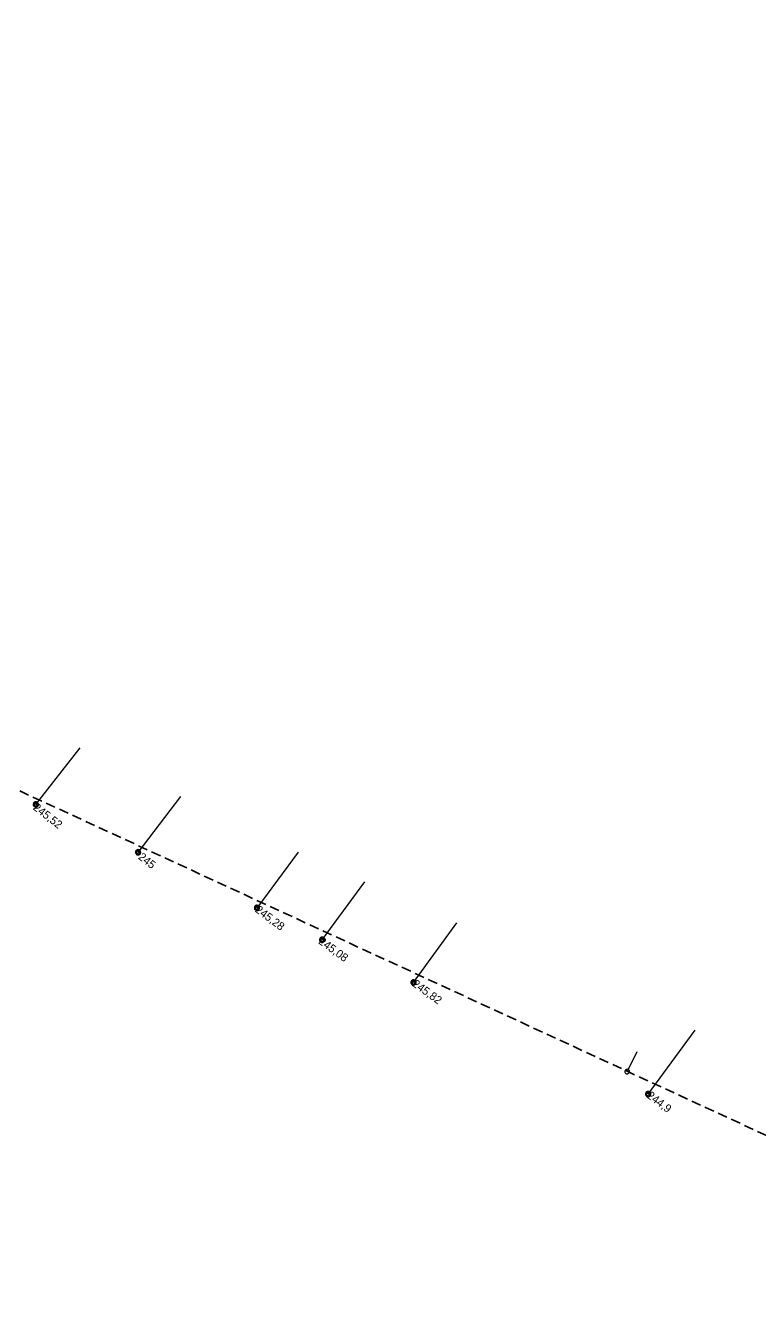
# Model space of a CAD drawing. Extents: x -735085 to -733500, y -1044153 to -1043402.
# Drawn here: x -734516.4 to -734443.8, y -1043690.4 to -1043562.9 of the extents above; entities that cross this region are included whole.
import ezdxf

# ---------------------------------------------------------------- set-up
doc = ezdxf.new("R2010")
doc.units = 0
doc.header["$LTSCALE"] = 0.32
doc.linetypes.add('MEDIUM_DASHED', pattern=[4.5, 3, -1.5])
doc.layers.add('16', color=7, linetype='Continuous')
for name, color, linetype, lineweight in [('18', 7, 'Continuous', 13), ('49', 7, 'Continuous', 13), ('63', 7, 'MEDIUM_DASHED', 25), ('8', 7, 'Continuous', 13)]:
    doc.layers.add(name, color=color, linetype=linetype, lineweight=lineweight)

msp = doc.modelspace()

# ---------------------------------------------------------------- linework, layer by layer
at = {"layer": '18'}
for points in [[(-734515.115, -1043640.239), (-734515.12, -1043640.183), (-734515.137, -1043640.13), (-734515.166, -1043640.081), (-734515.205, -1043640.04), (-734515.25, -1043640.008), (-734515.303, -1043639.986), (-734515.358, -1043639.975), (-734515.414, -1043639.977), (-734515.468, -1043639.99), (-734515.519, -1043640.015), (-734515.564, -1043640.05), (-734515.6, -1043640.093), (-734515.625, -1043640.143), (-734515.64, -1043640.198), (-734515.642, -1043640.254), (-734515.634, -1043640.309), (-734515.613, -1043640.362), (-734515.581, -1043640.408), (-734515.541, -1043640.447), (-734515.494, -1043640.477), (-734515.441, -1043640.496), (-734515.385, -1043640.503), (-734515.328, -1043640.499), (-734515.274, -1043640.482), (-734515.225, -1043640.455), (-734515.184, -1043640.417), (-734515.151, -1043640.372), (-734515.127, -1043640.321), (-734515.115, -1043640.266)], [(-734515.174, -1043640.242), (-734515.179, -1043640.193), (-734515.198, -1043640.147), (-734515.225, -1043640.106), (-734515.262, -1043640.073), (-734515.306, -1043640.051), (-734515.355, -1043640.039), (-734515.404, -1043640.039), (-734515.451, -1043640.051), (-734515.495, -1043640.074), (-734515.532, -1043640.107), (-734515.561, -1043640.148), (-734515.578, -1043640.195), (-734515.583, -1043640.244), (-734515.576, -1043640.293), (-734515.559, -1043640.339), (-734515.531, -1043640.379), (-734515.494, -1043640.412), (-734515.45, -1043640.434), (-734515.401, -1043640.446), (-734515.352, -1043640.445), (-734515.304, -1043640.433), (-734515.261, -1043640.409), (-734515.223, -1043640.376), (-734515.196, -1043640.335), (-734515.179, -1043640.288)], [(-734515.233, -1043640.246), (-734515.239, -1043640.204), (-734515.255, -1043640.166), (-734515.284, -1043640.135), (-734515.318, -1043640.112), (-734515.358, -1043640.101), (-734515.401, -1043640.101), (-734515.441, -1043640.113), (-734515.475, -1043640.136), (-734515.502, -1043640.168), (-734515.519, -1043640.206), (-734515.524, -1043640.247), (-734515.519, -1043640.289), (-734515.5, -1043640.326), (-734515.473, -1043640.358), (-734515.436, -1043640.38), (-734515.397, -1043640.391), (-734515.355, -1043640.39), (-734515.315, -1043640.377), (-734515.281, -1043640.354), (-734515.254, -1043640.321), (-734515.238, -1043640.283)], [(-734504.972, -1043644.989), (-734504.978, -1043644.933), (-734504.995, -1043644.88), (-734505.024, -1043644.831), (-734505.062, -1043644.79), (-734505.108, -1043644.758), (-734505.16, -1043644.736), (-734505.215, -1043644.725), (-734505.271, -1043644.727), (-734505.326, -1043644.74), (-734505.377, -1043644.765), (-734505.421, -1043644.8), (-734505.457, -1043644.843), (-734505.482, -1043644.893), (-734505.497, -1043644.948), (-734505.5, -1043645.004), (-734505.491, -1043645.059), (-734505.47, -1043645.112), (-734505.439, -1043645.158), (-734505.399, -1043645.197), (-734505.351, -1043645.227), (-734505.298, -1043645.246), (-734505.242, -1043645.253), (-734505.186, -1043645.249), (-734505.132, -1043645.232), (-734505.083, -1043645.205), (-734505.041, -1043645.167), (-734505.008, -1043645.122), (-734504.985, -1043645.071), (-734504.973, -1043645.016)], [(-734505.031, -1043644.992), (-734505.037, -1043644.943), (-734505.055, -1043644.897), (-734505.083, -1043644.856), (-734505.12, -1043644.823), (-734505.164, -1043644.801), (-734505.212, -1043644.789), (-734505.261, -1043644.789), (-734505.309, -1043644.801), (-734505.353, -1043644.824), (-734505.39, -1043644.857), (-734505.418, -1043644.898), (-734505.435, -1043644.945), (-734505.441, -1043644.994), (-734505.434, -1043645.043), (-734505.416, -1043645.089), (-734505.388, -1043645.129), (-734505.351, -1043645.162), (-734505.307, -1043645.184), (-734505.258, -1043645.196), (-734505.209, -1043645.195), (-734505.161, -1043645.183), (-734505.118, -1043645.159), (-734505.081, -1043645.126), (-734505.053, -1043645.085), (-734505.037, -1043645.038)], [(-734505.09, -1043644.996), (-734505.096, -1043644.954), (-734505.113, -1043644.916), (-734505.141, -1043644.885), (-734505.176, -1043644.862), (-734505.216, -1043644.851), (-734505.258, -1043644.851), (-734505.298, -1043644.863), (-734505.333, -1043644.886), (-734505.36, -1043644.918), (-734505.377, -1043644.956), (-734505.382, -1043644.997), (-734505.376, -1043645.039), (-734505.358, -1043645.076), (-734505.33, -1043645.108), (-734505.294, -1043645.13), (-734505.254, -1043645.141), (-734505.212, -1043645.14), (-734505.172, -1043645.127), (-734505.138, -1043645.104), (-734505.111, -1043645.071), (-734505.095, -1043645.033)], [(-734493.168, -1043650.51), (-734493.174, -1043650.454), (-734493.191, -1043650.401), (-734493.22, -1043650.352), (-734493.258, -1043650.311), (-734493.304, -1043650.279), (-734493.356, -1043650.257), (-734493.411, -1043650.246), (-734493.467, -1043650.248), (-734493.522, -1043650.261), (-734493.573, -1043650.286), (-734493.617, -1043650.321), (-734493.653, -1043650.364), (-734493.678, -1043650.414), (-734493.693, -1043650.469), (-734493.696, -1043650.525), (-734493.687, -1043650.58), (-734493.666, -1043650.633), (-734493.635, -1043650.679), (-734493.595, -1043650.718), (-734493.547, -1043650.748), (-734493.494, -1043650.767), (-734493.438, -1043650.774), (-734493.382, -1043650.77), (-734493.328, -1043650.753), (-734493.279, -1043650.726), (-734493.237, -1043650.688), (-734493.204, -1043650.643), (-734493.181, -1043650.592), (-734493.169, -1043650.537)], [(-734493.227, -1043650.513), (-734493.233, -1043650.464), (-734493.251, -1043650.418), (-734493.279, -1043650.377), (-734493.316, -1043650.344), (-734493.36, -1043650.322), (-734493.408, -1043650.31), (-734493.457, -1043650.31), (-734493.505, -1043650.322), (-734493.549, -1043650.345), (-734493.586, -1043650.378), (-734493.614, -1043650.419), (-734493.631, -1043650.466), (-734493.637, -1043650.515), (-734493.63, -1043650.564), (-734493.612, -1043650.61), (-734493.584, -1043650.65), (-734493.547, -1043650.683), (-734493.503, -1043650.705), (-734493.454, -1043650.717), (-734493.405, -1043650.716), (-734493.357, -1043650.704), (-734493.314, -1043650.68), (-734493.277, -1043650.647), (-734493.249, -1043650.606), (-734493.233, -1043650.559)], [(-734493.286, -1043650.517), (-734493.292, -1043650.475), (-734493.309, -1043650.437), (-734493.337, -1043650.406), (-734493.372, -1043650.383), (-734493.412, -1043650.372), (-734493.454, -1043650.372), (-734493.494, -1043650.384), (-734493.529, -1043650.407), (-734493.556, -1043650.439), (-734493.573, -1043650.477), (-734493.578, -1043650.518), (-734493.572, -1043650.56), (-734493.554, -1043650.597), (-734493.526, -1043650.629), (-734493.49, -1043650.651), (-734493.45, -1043650.662), (-734493.408, -1043650.661), (-734493.368, -1043650.648), (-734493.334, -1043650.625), (-734493.307, -1043650.592), (-734493.291, -1043650.554)], [(-734486.699, -1043653.679), (-734486.705, -1043653.623), (-734486.722, -1043653.57), (-734486.75, -1043653.521), (-734486.789, -1043653.48), (-734486.835, -1043653.448), (-734486.887, -1043653.426), (-734486.942, -1043653.415), (-734486.998, -1043653.417), (-734487.053, -1043653.43), (-734487.103, -1043653.455), (-734487.148, -1043653.49), (-734487.184, -1043653.533), (-734487.209, -1043653.583), (-734487.224, -1043653.638), (-734487.227, -1043653.694), (-734487.218, -1043653.749), (-734487.197, -1043653.802), (-734487.166, -1043653.848), (-734487.125, -1043653.887), (-734487.078, -1043653.917), (-734487.025, -1043653.936), (-734486.969, -1043653.943), (-734486.913, -1043653.939), (-734486.858, -1043653.922), (-734486.809, -1043653.895), (-734486.768, -1043653.857), (-734486.735, -1043653.812), (-734486.712, -1043653.761), (-734486.7, -1043653.706)], [(-734486.758, -1043653.682), (-734486.764, -1043653.633), (-734486.782, -1043653.587), (-734486.809, -1043653.546), (-734486.847, -1043653.513), (-734486.891, -1043653.491), (-734486.939, -1043653.479), (-734486.988, -1043653.479), (-734487.036, -1043653.491), (-734487.08, -1043653.514), (-734487.117, -1043653.547), (-734487.145, -1043653.588), (-734487.162, -1043653.635), (-734487.168, -1043653.684), (-734487.161, -1043653.733), (-734487.143, -1043653.779), (-734487.115, -1043653.819), (-734487.078, -1043653.852), (-734487.034, -1043653.874), (-734486.985, -1043653.886), (-734486.936, -1043653.885), (-734486.888, -1043653.873), (-734486.845, -1043653.849), (-734486.808, -1043653.816), (-734486.78, -1043653.775), (-734486.764, -1043653.728)], [(-734486.817, -1043653.686), (-734486.823, -1043653.644), (-734486.84, -1043653.606), (-734486.868, -1043653.575), (-734486.902, -1043653.552), (-734486.943, -1043653.541), (-734486.985, -1043653.541), (-734487.025, -1043653.553), (-734487.059, -1043653.576), (-734487.087, -1043653.608), (-734487.103, -1043653.646), (-734487.108, -1043653.687), (-734487.103, -1043653.729), (-734487.085, -1043653.766), (-734487.057, -1043653.798), (-734487.021, -1043653.82), (-734486.981, -1043653.831), (-734486.939, -1043653.83), (-734486.899, -1043653.817), (-734486.865, -1043653.794), (-734486.838, -1043653.761), (-734486.822, -1043653.723)], [(-734477.633, -1043657.901), (-734477.639, -1043657.845), (-734477.656, -1043657.792), (-734477.684, -1043657.743), (-734477.723, -1043657.702), (-734477.769, -1043657.67), (-734477.821, -1043657.648), (-734477.876, -1043657.637), (-734477.932, -1043657.639), (-734477.987, -1043657.652), (-734478.038, -1043657.677), (-734478.082, -1043657.712), (-734478.118, -1043657.755), (-734478.143, -1043657.805), (-734478.158, -1043657.86), (-734478.161, -1043657.916), (-734478.152, -1043657.971), (-734478.131, -1043658.024), (-734478.1, -1043658.07), (-734478.059, -1043658.109), (-734478.012, -1043658.139), (-734477.959, -1043658.158), (-734477.903, -1043658.165), (-734477.847, -1043658.161), (-734477.793, -1043658.144), (-734477.744, -1043658.117), (-734477.702, -1043658.079), (-734477.669, -1043658.034), (-734477.646, -1043657.983), (-734477.634, -1043657.928)], [(-734477.692, -1043657.904), (-734477.698, -1043657.855), (-734477.716, -1043657.809), (-734477.744, -1043657.768), (-734477.781, -1043657.735), (-734477.825, -1043657.713), (-734477.873, -1043657.701), (-734477.922, -1043657.701), (-734477.97, -1043657.713), (-734478.014, -1043657.736), (-734478.051, -1043657.769), (-734478.079, -1043657.81), (-734478.096, -1043657.857), (-734478.102, -1043657.906), (-734478.095, -1043657.955), (-734478.077, -1043658.001), (-734478.049, -1043658.041), (-734478.012, -1043658.074), (-734477.968, -1043658.096), (-734477.919, -1043658.108), (-734477.87, -1043658.107), (-734477.822, -1043658.095), (-734477.779, -1043658.071), (-734477.742, -1043658.038), (-734477.714, -1043657.997), (-734477.698, -1043657.95)], [(-734477.751, -1043657.908), (-734477.757, -1043657.866), (-734477.774, -1043657.828), (-734477.802, -1043657.797), (-734477.837, -1043657.774), (-734477.877, -1043657.763), (-734477.919, -1043657.763), (-734477.959, -1043657.775), (-734477.994, -1043657.798), (-734478.021, -1043657.83), (-734478.038, -1043657.868), (-734478.043, -1043657.909), (-734478.037, -1043657.951), (-734478.019, -1043657.988), (-734477.991, -1043658.02), (-734477.955, -1043658.042), (-734477.915, -1043658.053), (-734477.873, -1043658.052), (-734477.833, -1043658.039), (-734477.799, -1043658.016), (-734477.772, -1043657.983), (-734477.756, -1043657.945)], [(-734454.361, -1043669.001), (-734454.367, -1043668.945), (-734454.384, -1043668.892), (-734454.413, -1043668.843), (-734454.451, -1043668.802), (-734454.497, -1043668.77), (-734454.549, -1043668.748), (-734454.604, -1043668.737), (-734454.66, -1043668.739), (-734454.715, -1043668.752), (-734454.766, -1043668.777), (-734454.81, -1043668.812), (-734454.846, -1043668.855), (-734454.871, -1043668.905), (-734454.886, -1043668.96), (-734454.889, -1043669.016), (-734454.88, -1043669.071), (-734454.859, -1043669.124), (-734454.828, -1043669.17), (-734454.788, -1043669.209), (-734454.74, -1043669.239), (-734454.687, -1043669.258), (-734454.631, -1043669.265), (-734454.575, -1043669.261), (-734454.521, -1043669.244), (-734454.472, -1043669.217), (-734454.43, -1043669.179), (-734454.397, -1043669.134), (-734454.374, -1043669.083), (-734454.362, -1043669.028)], [(-734454.42, -1043669.004), (-734454.426, -1043668.955), (-734454.444, -1043668.909), (-734454.472, -1043668.868), (-734454.509, -1043668.835), (-734454.553, -1043668.813), (-734454.601, -1043668.801), (-734454.65, -1043668.801), (-734454.698, -1043668.813), (-734454.742, -1043668.836), (-734454.779, -1043668.869), (-734454.807, -1043668.91), (-734454.824, -1043668.957), (-734454.83, -1043669.006), (-734454.823, -1043669.055), (-734454.805, -1043669.101), (-734454.777, -1043669.141), (-734454.74, -1043669.174), (-734454.696, -1043669.196), (-734454.647, -1043669.208), (-734454.598, -1043669.207), (-734454.55, -1043669.195), (-734454.507, -1043669.171), (-734454.47, -1043669.138), (-734454.442, -1043669.097), (-734454.426, -1043669.05)], [(-734454.479, -1043669.008), (-734454.485, -1043668.966), (-734454.502, -1043668.928), (-734454.53, -1043668.897), (-734454.565, -1043668.874), (-734454.605, -1043668.863), (-734454.647, -1043668.863), (-734454.687, -1043668.875), (-734454.722, -1043668.898), (-734454.749, -1043668.93), (-734454.766, -1043668.968), (-734454.771, -1043669.009), (-734454.765, -1043669.051), (-734454.747, -1043669.088), (-734454.719, -1043669.12), (-734454.683, -1043669.142), (-734454.643, -1043669.153), (-734454.601, -1043669.152), (-734454.561, -1043669.139), (-734454.527, -1043669.116), (-734454.5, -1043669.083), (-734454.484, -1043669.045)]]:
    msp.add_lwpolyline(points, close=True, dxfattribs=at)
at = {"layer": '49'}
for p, q in [((-734515.379, -1043640.252), (-734510.977, -1043634.607)), ((-734515.379, -1043640.252), (-734510.977, -1043634.607)), ((-734505.236, -1043645.002), (-734500.989, -1043639.448)), ((-734505.236, -1043645.002), (-734500.989, -1043639.448)), ((-734493.432, -1043650.523), (-734489.306, -1043644.974)), ((-734493.432, -1043650.523), (-734489.306, -1043644.974)), ((-734486.963, -1043653.692), (-734482.734, -1043647.916)), ((-734486.963, -1043653.692), (-734482.734, -1043647.916)), ((-734477.897, -1043657.914), (-734473.607, -1043652.001)), ((-734477.897, -1043657.914), (-734473.607, -1043652.001)), ((-734454.625, -1043669.014), (-734449.947, -1043662.655)), ((-734454.625, -1043669.014), (-734449.947, -1043662.655))]:
    msp.add_line(p, q, dxfattribs=at)
at = {"layer": '63'}
msp.add_lwpolyline([(-734957.565, -1043435.501), (-734250.468, -1043761.931)], dxfattribs=at)
at = {"layer": '8'}
msp.add_line((-734455.73, -1043664.79), (-734456.69, -1043666.767), dxfattribs=at)
msp.add_lwpolyline([(-734456.599, -1043666.554), (-734456.648, -1043666.537), (-734456.701, -1043666.531), (-734456.753, -1043666.537), (-734456.803, -1043666.556), (-734456.847, -1043666.584), (-734456.883, -1043666.623), (-734456.91, -1043666.667), (-734456.926, -1043666.717), (-734456.93, -1043666.77), (-734456.922, -1043666.822), (-734456.902, -1043666.871), (-734456.873, -1043666.914), (-734456.833, -1043666.949), (-734456.788, -1043666.974), (-734456.737, -1043666.99), (-734456.685, -1043666.992), (-734456.633, -1043666.983), (-734456.584, -1043666.962), (-734456.543, -1043666.931), (-734456.508, -1043666.891), (-734456.484, -1043666.845), (-734456.47, -1043666.794), (-734456.469, -1043666.741), (-734456.48, -1043666.69), (-734456.502, -1043666.643), (-734456.534, -1043666.601), (-734456.575, -1043666.568)], close=True, dxfattribs=at)

# ---------------------------------------------------------------- texts
at = {"layer": '16'}
for s, rotation, p in [('245,52', 322, (-734515.721, -1043640.684)), ('245 ', 322, (-734505.285, -1043645.588)), ('245,28', 323, (-734493.688, -1043650.839)), ('245,08', 324, (-734487.402, -1043653.989)), ('245,82', 324, (-734478.098, -1043658.203)), ('244,9 ', 323, (-734454.818, -1043669.281))]:
    msp.add_text(s, height=0.8, rotation=rotation, dxfattribs=at).set_placement(p)

doc.saveas('drawing.dxf')
